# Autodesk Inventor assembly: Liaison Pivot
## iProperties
Author: Chris...
Shininess: 21.0
PropertySet Name: _Private Model Information
Created: 2002-01
Part Number: Liaison Pivot
Document SubType Name: Assemblage
Designer: Chris...
Control State: 0
Master: False
Checked Out: False
PropertySet Name: Design Tracking Control
Density: 0.0
Volumn: 0.0
Area: 0.0
PropertySet Name: Model Information
